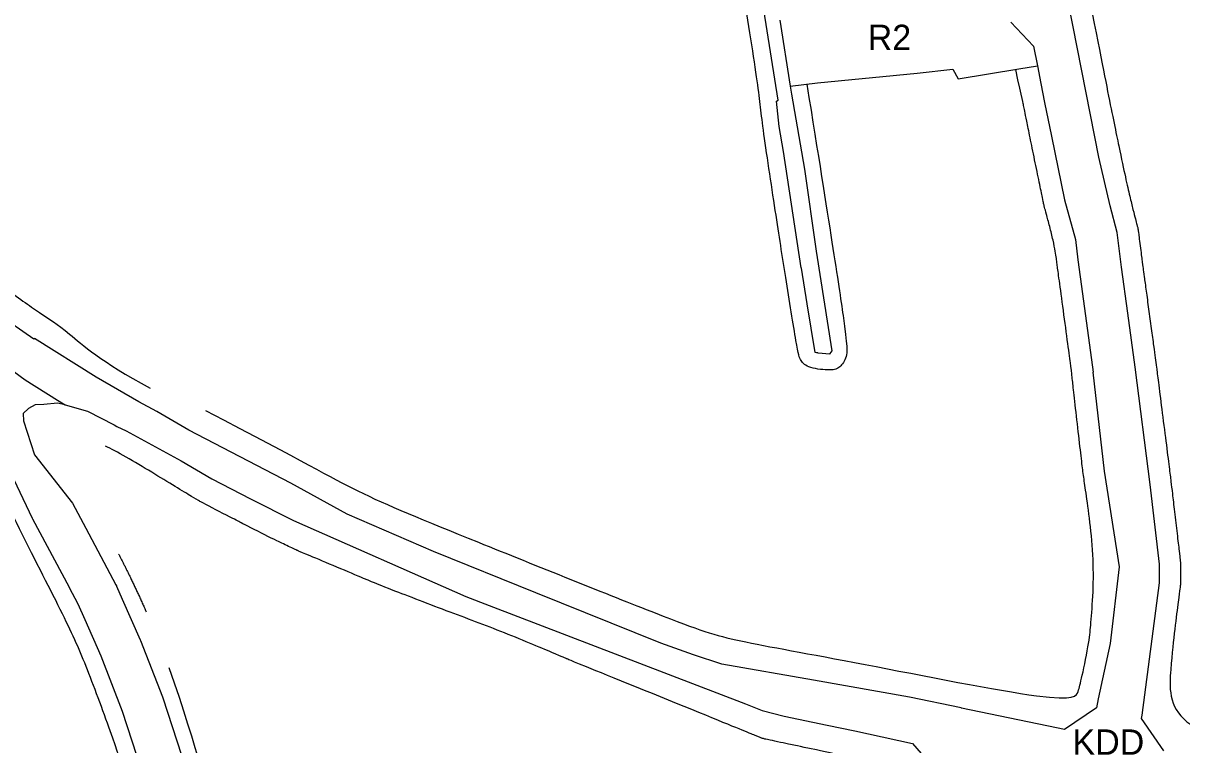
# Model space of a CAD drawing. Extents: x 7413438 to 7416393, y 5541665 to 5544118.
# Drawn here: x 7415261.6 to 7415535.1, y 5542473.3 to 5542643.7 of the extents above; entities that cross this region are included whole.
import ezdxf

# ---------------------------------------------------------------- set-up
doc = ezdxf.new("R2010")
doc.units = 0
for name, color, linetype in [('linie_rozgraniczajace', 7, 'Continuous'), ('linie_zabudowy_nieprzekraczalne', 7, 'Continuous'), ('oznaczenia_przeznaczen', 7, 'Continuous')]:
    doc.layers.add(name, color=color, linetype=linetype)

msp = doc.modelspace()

# ---------------------------------------------------------------- linework, layer by layer
at = {"layer": 'linie_rozgraniczajace'}
for p, q in [((7415439.82, 5542625.47), (7415436.45, 5542646.82)), ((7415440.19, 5542644.36), (7415442.67, 5542628.8)), ((7415494.75, 5542643.93), (7415500.11, 5542638.22)), ((7415509.47, 5542642.77), (7415508.93, 5542645.54)), ((7415515.57, 5542612.06), (7415509.47, 5542642.77)), ((7415500.11, 5542638.22), (7415501.03, 5542633.61)), ((7415472.66, 5542631.89), (7415481.1, 5542632.81)), ((7415481.1, 5542632.81), (7415482.31, 5542630.52)), ((7415482.31, 5542630.52), (7415496.66, 5542632.89)), ((7415496.66, 5542632.89), (7415501.03, 5542633.61)), ((7415501.03, 5542633.61), (7415501.86, 5542629.43)), ((7415442.67, 5542628.8), (7415449.1, 5542629.61)), ((7415449.1, 5542629.61), (7415472.66, 5542631.89)), ((7415501.86, 5542629.43), (7415502.72, 5542624.96)), ((7415442.67, 5542628.8), (7415442.97, 5542626.88)), ((7415442.97, 5542626.88), (7415446.01, 5542609.16)), ((7415439.4, 5542625.28), (7415439.82, 5542625.47)), ((7415440.08, 5542619.29), (7415439.4, 5542625.28)), ((7415502.72, 5542624.96), (7415504.36, 5542616.96)), ((7415441.07, 5542613.34), (7415440.08, 5542619.29)), ((7415504.36, 5542616.96), (7415507.44, 5542601.96)), ((7415445.29, 5542585.89), (7415441.07, 5542613.34)), ((7415518.21, 5542600.51), (7415515.57, 5542612.06)), ((7415446.01, 5542609.16), (7415448.82, 5542589.8)), ((7415507.44, 5542601.96), (7415510, 5542592.62)), ((7415519.87, 5542594.22), (7415518.21, 5542600.51)), ((7415520.9, 5542586.06), (7415519.87, 5542594.22)), ((7415510, 5542592.62), (7415510.6, 5542587.81)), ((7415448.82, 5542589.8), (7415452.51, 5542566.31)), ((7415445.3, 5542585.84), (7415445.29, 5542585.89)), ((7415446.67, 5542577.38), (7415445.3, 5542585.84)), ((7415510.6, 5542587.81), (7415511.69, 5542579.78)), ((7415520.91, 5542586.06), (7415520.9, 5542586.06)), ((7415522.39, 5542575.15), (7415520.91, 5542586.06)), ((7415448.53, 5542565.87), (7415446.67, 5542577.38)), ((7415511.69, 5542579.78), (7415514.19, 5542561.29)), ((7415264.06, 5542569.04), (7415253.05, 5542576.7)), ((7415524.12, 5542562.46), (7415522.39, 5542575.15)), ((7415264.21, 5542569.23), (7415264.06, 5542569.04)), ((7415278.83, 5542560.07), (7415264.21, 5542569.23)), ((7415452.51, 5542566.31), (7415452, 5542565.63)), ((7415255.33, 5542564.35), (7415262.03, 5542559.44)), ((7415448.87, 5542565.85), (7415448.53, 5542565.87)), ((7415449.21, 5542565.82), (7415448.87, 5542565.85)), ((7415449.23, 5542565.74), (7415449.21, 5542565.82)), ((7415449.26, 5542565.77), (7415449.23, 5542565.74)), ((7415452.02, 5542565.54), (7415449.26, 5542565.77)), ((7415452, 5542565.63), (7415452.01, 5542565.62)), ((7415452.01, 5542565.62), (7415452.02, 5542565.54)), ((7415514.19, 5542561.29), (7415514.13, 5542561.29)), ((7415514.13, 5542561.29), (7415516.8, 5542537.89)), ((7415524.12, 5542562.44), (7415524.12, 5542562.46)), ((7415527.64, 5542534.7), (7415524.12, 5542562.44)), ((7415262.03, 5542559.44), (7415269.66, 5542554.66)), ((7415288.87, 5542554.28), (7415278.83, 5542560.07)), ((7415262.79, 5542552.7), (7415261.6, 5542551.47)), ((7415264.39, 5542553.58), (7415262.79, 5542552.7)), ((7415266.45, 5542553.66), (7415264.39, 5542553.58)), ((7415269.71, 5542553.9), (7415266.45, 5542553.66)), ((7415269.66, 5542554.66), (7415271.45, 5542553.57)), ((7415271.45, 5542553.57), (7415269.71, 5542553.9)), ((7415271.45, 5542553.57), (7415276.73, 5542552.06)), ((7415293.15, 5542551.94), (7415288.87, 5542554.28)), ((7415261.6, 5542551.47), (7415261.62, 5542549.76)), ((7415276.73, 5542552.06), (7415283.04, 5542548.8)), ((7415300.65, 5542547.54), (7415293.15, 5542551.94)), ((7415261.62, 5542549.76), (7415264.22, 5542541.76)), ((7415283.04, 5542548.8), (7415283.71, 5542548.44)), ((7415283.71, 5542548.44), (7415285.92, 5542547.41)), ((7415285.92, 5542547.41), (7415298.87, 5542540.3)), ((7415324.79, 5542535.05), (7415300.65, 5542547.54)), ((7415263.79, 5542526.73), (7415256.53, 5542541.94)), ((7415264.22, 5542541.76), (7415273.18, 5542530.36)), ((7415298.87, 5542540.3), (7415306.11, 5542536.08)), ((7415516.8, 5542537.89), (7415520.32, 5542515.33)), ((7415306.11, 5542536.08), (7415315.21, 5542531.36)), ((7415338.05, 5542527.73), (7415324.79, 5542535.05)), ((7415529.83, 5542515.93), (7415527.64, 5542534.7)), ((7415315.21, 5542531.36), (7415325.37, 5542526.25)), ((7415273.18, 5542530.36), (7415276.36, 5542524.4)), ((7415263.89, 5542526.54), (7415263.79, 5542526.73)), ((7415272.49, 5542510.38), (7415263.89, 5542526.54)), ((7415325.37, 5542526.25), (7415366.1, 5542508.31)), ((7415358.42, 5542518.95), (7415338.05, 5542527.73)), ((7415276.36, 5542524.4), (7415283.47, 5542511.05)), ((7415382.59, 5542509.16), (7415358.42, 5542518.95)), ((7415520.32, 5542515.33), (7415518.24, 5542497.18)), ((7415529.83, 5542511.55), (7415529.83, 5542515.93)), ((7415272.51, 5542510.36), (7415272.49, 5542510.38)), ((7415274.55, 5542506.51), (7415272.51, 5542510.36)), ((7415283.47, 5542511.05), (7415283.59, 5542510.8)), ((7415283.59, 5542510.8), (7415283.63, 5542510.71)), ((7415283.63, 5542510.71), (7415284.98, 5542507.63)), ((7415412.15, 5542497.31), (7415382.59, 5542509.16)), ((7415525.73, 5542480.29), (7415529.83, 5542511.55)), ((7415276.19, 5542502.78), (7415274.55, 5542506.51)), ((7415284.98, 5542507.63), (7415289.17, 5542498.09)), ((7415366.1, 5542508.31), (7415371.56, 5542506.2)), ((7415371.56, 5542506.2), (7415432.08, 5542482.95)), ((7415279.97, 5542494.17), (7415276.19, 5542502.78)), ((7415289.17, 5542498.09), (7415289.25, 5542497.89)), ((7415289.25, 5542497.89), (7415294.43, 5542484.6)), ((7415419.86, 5542494.48), (7415412.15, 5542497.31)), ((7415518.24, 5542497.18), (7415515.41, 5542484.09)), ((7415285.06, 5542481.1), (7415279.97, 5542494.17)), ((7415426.51, 5542492.28), (7415419.86, 5542494.48)), ((7415448.2, 5542488.53), (7415426.51, 5542492.28)), ((7415470.87, 5542484.49), (7415448.2, 5542488.53)), ((7415294.43, 5542484.6), (7415294.43, 5542484.58)), ((7415294.43, 5542484.58), (7415294.52, 5542484.34)), ((7415294.52, 5542484.34), (7415298.94, 5542470.8)), ((7415483.04, 5542481.97), (7415470.87, 5542484.49)), ((7415432.08, 5542482.95), (7415436.01, 5542481.35)), ((7415483.12, 5542481.95), (7415483.04, 5542481.97)), ((7415505.54, 5542477.31), (7415483.12, 5542481.95)), ((7415514.99, 5542482.03), (7415507.4, 5542476.92)), ((7415515.41, 5542484.09), (7415514.99, 5542482.03)), ((7415289.72, 5542466.81), (7415285.06, 5542481.1)), ((7415436.01, 5542481.35), (7415441.23, 5542480.07)), ((7415441.23, 5542480.07), (7415451.39, 5542477.95)), ((7415525.64, 5542479.52), (7415525.73, 5542480.29)), ((7415530.9, 5542471.89), (7415525.64, 5542479.52)), ((7415451.39, 5542477.95), (7415457.92, 5542476.57)), ((7415457.92, 5542476.57), (7415461.16, 5542475.87)), ((7415505.56, 5542477.3), (7415505.54, 5542477.31)), ((7415507.4, 5542476.92), (7415505.56, 5542477.3)), ((7415461.16, 5542475.87), (7415471.51, 5542473.55)), ((7415471.51, 5542473.55), (7415478.79, 5542465.23))]:
    msp.add_line(p, q, dxfattribs=at)
at = {"layer": 'linie_zabudowy_nieprzekraczalne'}
for points, degree in [([(7415446.6, 5542629.27), (7415452.04, 5542595.33), (7415456.18, 5542568.61), (7415456.15, 5542564.66), (7415454.36, 5542562.27), (7415452.69, 5542561.56), (7415446.89, 5542562.18), (7415445, 5542563.92), (7415444.43, 5542566.07), (7415441.46, 5542584.43), (7415439.41, 5542597.71), (7415435.8, 5542621.33), (7415435.43, 5542627.48), (7415430.97, 5542654.89), (7415428.14, 5542671.28), (7415426.81, 5542679.05), (7415422.91, 5542706.51), (7415422.23, 5542712.31), (7415420.9, 5542715.65), (7415415.52, 5542727.29), (7415409.38, 5542740.3), (7415403.87, 5542751.75), (7415396.65, 5542765.15), (7415393.99, 5542770.37), (7415392.24, 5542774.92), (7415389.31, 5542782.59), (7415382.93, 5542798.83), (7415380.52, 5542804.19)], 3), ([(7415060.2, 5542700.03), (7415063.8, 5542694.82), (7415069.96, 5542687.2), (7415074.97, 5542682.48), (7415094.07, 5542670.45), (7415095.67, 5542670.19), (7415115.82, 5542663.31), (7415160.33, 5542649.35), (7415173.61, 5542643.76), (7415176.31, 5542642.11), (7415190.15, 5542632.51), (7415210.39, 5542618.3), (7415230.16, 5542603.31), (7415243.83, 5542592.3), (7415246.54, 5542589.46), (7415257.35, 5542580.95), (7415265.92, 5542574.94), (7415271.31, 5542571.58), (7415279.78, 5542563.89), (7415291.54, 5542557.48)], 3), ([(7415511.02, 5542661.49), (7415514.82, 5542641.66), (7415518.03, 5542625.4), (7415520.38, 5542613.91), (7415521.88, 5542606.92), (7415522.86, 5542602.65), (7415523.63, 5542599.54), (7415524.21, 5542597.31), (7415524.55, 5542596.01), (7415524.69, 5542595.48), (7415524.73, 5542595.33), (7415524.75, 5542595.24), (7415524.77, 5542595.12), (7415524.79, 5542595.01), (7415524.84, 5542594.68), (7415524.96, 5542593.68), (7415525.22, 5542591.69), (7415525.51, 5542589.37), (7415525.72, 5542587.69), (7415525.81, 5542587), (7415525.83, 5542586.86), (7415525.85, 5542586.73), (7415525.95, 5542586), (7415526.22, 5542584), (7415526.69, 5542580.57), (7415527.28, 5542576.2), (7415527.92, 5542571.51), (7415528.49, 5542567.31), (7415528.88, 5542564.47), (7415529.12, 5542562.61), (7415529.54, 5542559.36), (7415530.37, 5542552.75), (7415531.4, 5542544.63), (7415532.19, 5542538.42), (7415532.57, 5542535.35), (7415532.87, 5542532.85), (7415533.39, 5542528.45), (7415534.03, 5542522.94), (7415534.53, 5542518.68), (7415534.74, 5542516.81), (7415534.79, 5542516.39), (7415534.8, 5542516.31), (7415534.81, 5542516.2), (7415534.81, 5542516.09), (7415534.82, 5542515.91), (7415534.82, 5542515.42), (7415534.82, 5542514.39), (7415534.82, 5542513.09), (7415534.82, 5542512.04), (7415534.82, 5542511.55), (7415534.81, 5542511.38), (7415534.81, 5542511.28), (7415534.8, 5542511.17), (7415534.79, 5542511.06), (7415534.72, 5542510.45), (7415534.35, 5542507.63), (7415533.49, 5542500.98), (7415532.47, 5542491.97), (7415531.63, 5542477.4), (7415559.07, 5542470.57), (7415584.68, 5542465.35), (7415619.26, 5542458.32), (7415619.26, 5542458.32), (7415651.48, 5542451.74), (7415651.6, 5542451.72), (7415651.67, 5542451.7), (7415702.44, 5542439.32), (7415707.66, 5542438.37), (7415707.77, 5542438.33), (7415727.6, 5542432.09), (7415757.24, 5542424.08), (7415775.01, 5542419.29), (7415812.56, 5542410.29), (7415812.58, 5542410.29), (7415831.04, 5542405.78), (7415848.22, 5542401.59), (7415877.11, 5542394.69), (7415893.94, 5542390.97), (7415909.41, 5542389.1), (7415919.17, 5542387.92), (7415919.38, 5542387.89), (7415950.44, 5542383.02)], 3), ([(7415304.62, 5542552.19), (7415328.5, 5542539.81), (7415338.99, 5542533.3), (7415364.29, 5542523), (7415418.06, 5542501.35), (7415427.96, 5542498.07), (7415456.12, 5542493.22), (7415509.56, 5542482.46), (7415510.72, 5542486.08), (7415511.39, 5542488.43), (7415513.44, 5542498.39), (7415513.55, 5542501.37), (7415514.31, 5542509.25), (7415514.25, 5542518.12), (7415513.33, 5542527.17), (7415512.34, 5542533.93), (7415511.84, 5542537.28), (7415511.41, 5542540.91), (7415510.59, 5542548.03), (7415509.72, 5542555.69), (7415509.26, 5542559.78), (7415509.15, 5542560.74), (7415509.14, 5542560.85), (7415509.13, 5542560.98), (7415509.12, 5542561.19), (7415508.91, 5542562.83), (7415508.17, 5542568.38), (7415506.99, 5542577.13), (7415506.03, 5542584.19), (7415505.66, 5542586.98), (7415505.52, 5542588.01), (7415505.28, 5542589.66), (7415504.77, 5542592.29), (7415503.93, 5542595.7), (7415503.11, 5542598.76), (7415502.68, 5542600.33), (7415502.58, 5542600.73), (7415502.54, 5542600.89), (7415502.29, 5542602.12), (7415501.53, 5542605.81), (7415500.37, 5542611.44), (7415499.26, 5542616.87), (7415498.45, 5542620.79), (7415497.99, 5542623.06), (7415497.78, 5542624.11), (7415497.54, 5542625.32), (7415495.9, 5542632.73)], 3), ([(7415478.14, 5542395.8), (7415478.06, 5542396.84), (7415477.96, 5542398.15), (7415477.92, 5542398.77), (7415477.85, 5542399.82), (7415477.71, 5542402.13), (7415477.45, 5542406.25), (7415477.08, 5542411.94), (7415476.65, 5542418.47), (7415476.26, 5542424.37), (7415476.03, 5542427.81), (7415475.93, 5542429.28), (7415475.82, 5542431.19), (7415475.58, 5542435.34), (7415475.13, 5542442.73), (7415474.55, 5542452.09), (7415474.12, 5542459.05), (7415473.97, 5542461.58), (7415473.94, 5542462.08), (7415473.56, 5542466.85), (7415443.92, 5542473.1), (7415443.91, 5542473.1), (7415436.79, 5542474.61), (7415436.72, 5542474.62), (7415436.34, 5542474.72), (7415435.97, 5542474.85), (7415435.77, 5542474.92), (7415429.8, 5542477.35), (7415390.21, 5542493.45), (7415390.11, 5542493.49), (7415388.58, 5542494.15), (7415374.13, 5542500.26), (7415361.02, 5542505.05), (7415345.22, 5542511.19), (7415345.06, 5542511.25), (7415326.25, 5542519.17), (7415326.15, 5542519.22), (7415326.02, 5542519.27), (7415321.61, 5542521.35), (7415321.46, 5542521.43), (7415312.48, 5542525.97), (7415312.43, 5542525.99), (7415303.33, 5542530.71), (7415303.3, 5542530.73), (7415303.07, 5542530.86), (7415292.32, 5542537.4), (7415283.52, 5542542.68), (7415280.98, 5542543.75)], 3), ([(7415354.02, 5542157.54), (7415351.12, 5542172.84), (7415343.57, 5542209.73), (7415339.4, 5542229.81), (7415336.1, 5542245.87), (7415329.78, 5542276.17), (7415325.62, 5542295.99), (7415324.08, 5542302.96), (7415325.54, 5542310.25), (7415322.96, 5542316.74), (7415320.29, 5542324.11), (7415316.96, 5542335.38), (7415310.62, 5542361.08), (7415303.17, 5542393.62), (7415293.51, 5542434.1), (7415288.48, 5542454.95), (7415286.07, 5542465.01), (7415283.42, 5542473.12), (7415276.7, 5542491.46), (7415272.35, 5542501.51), (7415261.71, 5542522.05), (7415253.51, 5542538.9), (7415250.76, 5542540.28)], 3), ([(7415284.11, 5542518.28), (7415287.27, 5542512.28), (7415290.6, 5542504.7)], 2), ([(7415295.99, 5542491.53), (7415302.85, 5542471.62), (7415308.05, 5542450.54), (7415314.21, 5542425.2), (7415323.86, 5542383.92), (7415331.41, 5542351.5), (7415333.83, 5542341.8), (7415336.46, 5542332.92), (7415338.78, 5542325.68), (7415342.46, 5542316.58), (7415345.14, 5542310.89), (7415347.54, 5542305.82), (7415350, 5542299.91), (7415352.77, 5542292.36), (7415355.49, 5542284.28), (7415358.59, 5542273.88), (7415361.68, 5542261.19), (7415364.65, 5542247.55), (7415369.56, 5542224.21), (7415371.28, 5542215.68), (7415372.37, 5542210.66), (7415373.22, 5542207.57), (7415375.86, 5542200.38), (7415379.74, 5542190.22), (7415382.99, 5542181.86), (7415385.67, 5542175.87), (7415392.06, 5542162.91), (7415396.28, 5542155.91), (7415400.54, 5542148.84), (7415409.48, 5542134.31), (7415416.95, 5542121.74), (7415427, 5542104.71), (7415427.44, 5542103.88), (7415430.21, 5542102.63), (7415445.54, 5542107.53), (7415455.72, 5542110.79), (7415466.45, 5542114.94), (7415481.49, 5542125.25), (7415498.78, 5542137.78), (7415505.24, 5542143.35), (7415506.64, 5542150.49), (7415507.47, 5542153.2), (7415507.59, 5542156.4), (7415509.01, 5542160.12), (7415514.59, 5542173.7), (7415516.59, 5542179.22), (7415519.53, 5542190.38), (7415521.31, 5542196.94), (7415521.5, 5542202.22), (7415520.65, 5542207.52), (7415519.83, 5542212.18), (7415520.24, 5542219.81), (7415520.01, 5542222.73), (7415518.69, 5542226.87), (7415516.28, 5542232.53), (7415511.98, 5542246.23), (7415509.64, 5542254.02), (7415509.63, 5542256.3), (7415510.53, 5542257.88), (7415511.79, 5542258.8), (7415513.31, 5542259.37), (7415515.21, 5542269.39), (7415515.87, 5542274.11), (7415515.45, 5542280.92), (7415513.62, 5542292.38), (7415511.18, 5542306.13), (7415512.31, 5542312.21), (7415513.08, 5542313.79), (7415514.76, 5542315.01), (7415525.18, 5542321.62), (7415520.14, 5542332.18), (7415500.04, 5542355.68), (7415493.33, 5542363.63), (7415486.15, 5542374.99)], 3)]:
    msp.add_open_spline(points, degree=degree, dxfattribs=at)

# ---------------------------------------------------------------- texts
at = {"layer": 'oznaczenia_przeznaczen'}
for s, p in [('R2', (7415460.97, 5542637.3)), ('KDD', (7415509.32, 5542470.92))]:
    msp.add_text(s, height=6, dxfattribs=at).set_placement(p)

doc.saveas('drawing.dxf')
